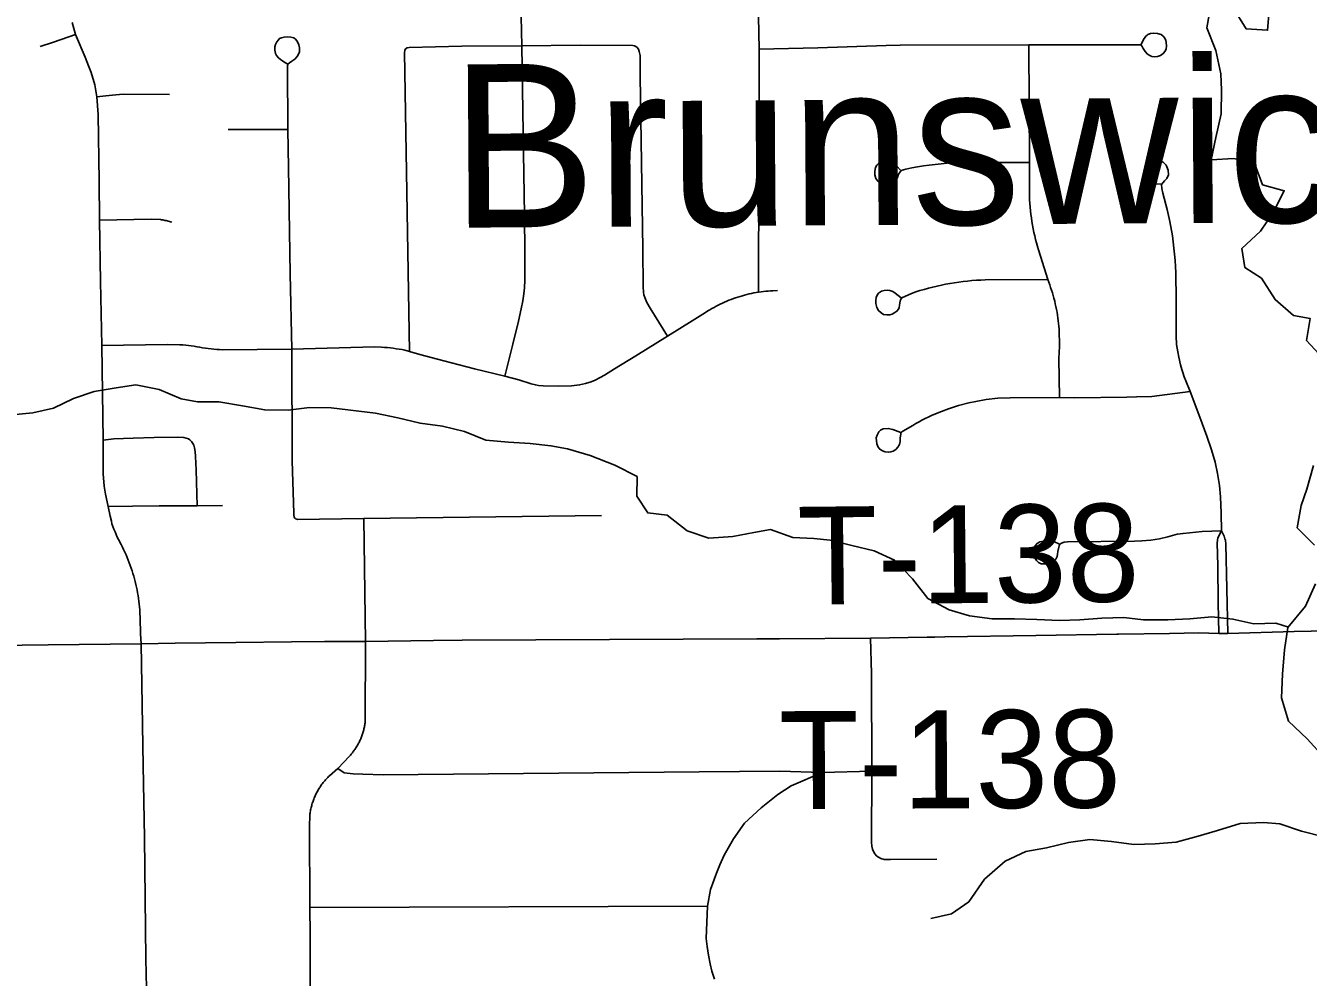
# Model space of a CAD drawing. Extents: x 0 to 34, y 0 to 22.
# Drawn here: x 5.7025 to 6.0747, y 18.6634 to 18.9395 of the extents above; entities that cross this region are included whole.
import ezdxf

# ---------------------------------------------------------------- set-up
doc = ezdxf.new("R2010")
doc.units = 0
for name, color, linetype in [('GM_X_City_Street', 7, 'Continuous'), ('GM_X_Minor_Lake_Text', 7, 'Continuous'), ('GM_X_Minor_River', 7, 'Continuous'), ('GM_X_Township_Road', 7, 'Continuous'), ('GM_X_Township_Road_Text', 7, 'Continuous')]:
    doc.layers.add(name, color=color, linetype=linetype)

msp = doc.modelspace()

# ---------------------------------------------------------------- linework, layer by layer
at = {"layer": 'GM_X_City_Street'}
for p, q in [((5.76126, 18.90929), (5.77862, 18.90938)), ((5.78502, 18.6836), (5.90037, 18.68403))]:
    msp.add_line(p, q, dxfattribs=at)
for points in [[(5.84161, 18.83777), (5.84393, 18.84708), (5.84551, 18.85371), (5.84628, 18.85726), (5.84675, 18.85966), (5.84705, 18.86168), (5.84727, 18.86344), (5.84742, 18.86564), (5.84734, 18.87349), (5.84728, 18.8846), (5.84693, 18.90844), (5.84649, 18.93361), (5.84624, 18.94642), (5.84614, 18.96701), (5.84592, 18.97776), (5.846, 18.98047), (5.8461, 18.98159), (5.84646, 18.98369), (5.84742, 18.98739), (5.84751, 18.98842), (5.84733, 18.99027), (5.84712, 18.99152), (5.84692, 18.99229), (5.84633, 18.9937)], [(5.91519, 18.86214), (5.91534, 18.93265), (5.91473, 18.96601)], [(5.73602, 18.76015), (5.73586, 18.76297), (5.73578, 18.76754), (5.73571, 18.76919), (5.73566, 18.77002), (5.73559, 18.77084), (5.73551, 18.77166), (5.73541, 18.77248), (5.7353, 18.7733), (5.73517, 18.77412), (5.73503, 18.77493), (5.73488, 18.77574), (5.73471, 18.77655), (5.73453, 18.77735), (5.73434, 18.77816), (5.73412, 18.77895), (5.7339, 18.77975), (5.73367, 18.78054), (5.73342, 18.78132), (5.73316, 18.78211), (5.73289, 18.78289), (5.7326, 18.78366), (5.7323, 18.78443), (5.73198, 18.78519), (5.73166, 18.78595), (5.73132, 18.7867), (5.73096, 18.78745), (5.7306, 18.78818), (5.73021, 18.78894), (5.7295, 18.79034), (5.72914, 18.79109), (5.72881, 18.79184), (5.72848, 18.7926), (5.72816, 18.79336), (5.72786, 18.79413), (5.72757, 18.79491), (5.72746, 18.79571), (5.72705, 18.79719), (5.72645, 18.79995), (5.72569, 18.80357), (5.72536, 18.80587), (5.72506, 18.80944), (5.72507, 18.81917), (5.72465, 18.84665), (5.72429, 18.86527), (5.72398, 18.88306), (5.72389, 18.8943), (5.72354, 18.91373), (5.72321, 18.91879), (5.72266, 18.92226), (5.72152, 18.92588), (5.72075, 18.92785), (5.71977, 18.93031), (5.71704, 18.93693), (5.71601, 18.94037)], [(5.7068, 18.93339), (5.71061, 18.93471), (5.71704, 18.93693)], [(5.78061, 18.79658), (5.78048, 18.79685), (5.78042, 18.79711), (5.78039, 18.79729), (5.78031, 18.79807), (5.77986, 18.81325), (5.77974, 18.84565), (5.77932, 18.86749), (5.77876, 18.8983), (5.77862, 18.90938), (5.77847, 18.92759), (5.77865, 18.9283), (5.77905, 18.92864), (5.7798, 18.92919), (5.78062, 18.92975), (5.78136, 18.93051), (5.78175, 18.93119), (5.78196, 18.93187), (5.78203, 18.93238), (5.78199, 18.93306), (5.78183, 18.9339), (5.78154, 18.93456), (5.7812, 18.93503), (5.78088, 18.93553), (5.78034, 18.93589), (5.77948, 18.93612), (5.77866, 18.93619), (5.77751, 18.93617), (5.77677, 18.93592), (5.77615, 18.93569), (5.77586, 18.93531), (5.77539, 18.93481), (5.775, 18.93395), (5.77484, 18.93334), (5.77484, 18.93239), (5.77503, 18.93138), (5.7753, 18.93076), (5.77594, 18.93014), (5.77652, 18.92964), (5.77704, 18.92927), (5.77749, 18.92893), (5.77844, 18.9284)], [(5.91534, 18.93265), (5.93238, 18.93301), (5.95223, 18.93369), (5.95626, 18.93376), (5.99365, 18.93392), (6.02607, 18.93388), (6.02625, 18.9338), (6.02654, 18.93346), (6.02681, 18.93285), (6.02733, 18.93195), (6.02805, 18.93123), (6.02869, 18.93079), (6.02934, 18.93055), (6.03006, 18.93044), (6.03095, 18.93049), (6.03185, 18.93085), (6.03263, 18.93136), (6.03318, 18.93202), (6.03347, 18.93278), (6.03355, 18.93347), (6.03349, 18.93464), (6.03335, 18.93515), (6.03305, 18.93586), (6.03263, 18.93639), (6.03199, 18.93687), (6.03091, 18.9372), (6.02977, 18.93732), (6.02893, 18.93722), (6.02813, 18.93691), (6.0279, 18.93675), (6.02753, 18.93641), (6.02732, 18.93612), (6.02688, 18.93541), (6.0262, 18.93403)], [(5.81387, 18.84495), (5.8125, 18.93171), (5.81259, 18.9323), (5.81276, 18.93273)], [(5.81276, 18.93273), (5.81327, 18.933), (5.81381, 18.93309), (5.82913, 18.93348), (5.84649, 18.93361), (5.86341, 18.93377), (5.87875, 18.9337), (5.8792, 18.9336), (5.87958, 18.93345), (5.88001, 18.93317)], [(5.8888, 18.84933), (5.88372, 18.85747), (5.8828, 18.85917), (5.8822, 18.86057), (5.88195, 18.86139), (5.88182, 18.86215), (5.88171, 18.86365), (5.88161, 18.87471), (5.88085, 18.92476), (5.8808, 18.93076), (5.8806, 18.93196), (5.88032, 18.93263), (5.88001, 18.93317)], [(6.00248, 18.83158), (6.00234, 18.84291), (6.00248, 18.8464), (6.00239, 18.8514), (6.00233, 18.85223), (6.00225, 18.85305), (6.00216, 18.85387), (6.00205, 18.85469), (6.00193, 18.85551), (6.00179, 18.85632), (6.00165, 18.85714), (6.00148, 18.85795), (6.0013, 18.85875), (6.00111, 18.85956), (6.00091, 18.86036), (6.00069, 18.86115), (6.00045, 18.86195), (6.0002, 18.86273), (5.99994, 18.86352), (5.99967, 18.8643), (5.99938, 18.86507), (5.99914, 18.86584), (5.99702, 18.87259), (5.99644, 18.87439), (5.99613, 18.87541), (5.99585, 18.87643), (5.99558, 18.87744), (5.99534, 18.87847), (5.9951, 18.8795), (5.99489, 18.88054), (5.9947, 18.88158), (5.99452, 18.88262), (5.99436, 18.88366), (5.99422, 18.88471), (5.9941, 18.88576), (5.994, 18.88681), (5.99391, 18.88786), (5.99385, 18.88892), (5.9938, 18.88997), (5.99383, 18.89525), (5.99381, 18.8998), (5.99365, 18.93392)], [(5.72321, 18.91879), (5.72579, 18.9191), (5.72868, 18.91941), (5.7308, 18.91957), (5.74424, 18.91952)], [(5.95633, 18.89754), (5.95532, 18.89867), (5.95482, 18.8992), (5.95439, 18.89957), (5.95392, 18.89987), (5.9535, 18.90006), (5.95326, 18.90012), (5.95273, 18.9002), (5.95113, 18.90005), (5.95051, 18.89983), (5.94999, 18.89948), (5.94949, 18.899), (5.94916, 18.89835), (5.94891, 18.89727), (5.94896, 18.89618), (5.94925, 18.8951), (5.94977, 18.89432), (5.95033, 18.8939), (5.95097, 18.89359), (5.95153, 18.89345), (5.95202, 18.89337), (5.95336, 18.89347), (5.95396, 18.89371), (5.95485, 18.89445), (5.95548, 18.89542), (5.95581, 18.89633), (5.95604, 18.89675), (5.95658, 18.89744), (5.95793, 18.89785), (5.95962, 18.89818), (5.96132, 18.89848), (5.96302, 18.89875), (5.96473, 18.89898), (5.96644, 18.89919), (5.96816, 18.89937), (5.96988, 18.89952), (5.9716, 18.89964), (5.97332, 18.89973), (5.97504, 18.89979), (5.99381, 18.8998)], [(6.0495, 18.7929), (6.04941, 18.79799), (6.04926, 18.80277), (6.04893, 18.80602), (6.04833, 18.80953), (6.04763, 18.81286), (6.04657, 18.81637), (6.04523, 18.8204), (6.04319, 18.8259), (6.04038, 18.83328), (6.03912, 18.83644), (6.03872, 18.83755), (6.0383, 18.83887), (6.03801, 18.83968), (6.0376, 18.84104), (6.03709, 18.84331), (6.0368, 18.84484), (6.03648, 18.847), (6.03634, 18.84941), (6.03639, 18.85461), (6.03633, 18.86171), (6.03629, 18.86596), (6.03624, 18.86775), (6.03616, 18.86955), (6.03604, 18.87134), (6.0359, 18.87313), (6.03572, 18.87492), (6.03551, 18.8767), (6.03527, 18.87848), (6.03455, 18.88267), (6.03379, 18.88611), (6.03252, 18.89083), (6.03219, 18.89224), (6.03212, 18.89341), (6.03296, 18.89444), (6.03362, 18.89516), (6.03411, 18.8962), (6.03405, 18.89755), (6.0335, 18.89901), (6.0326, 18.89989), (6.03126, 18.90038), (6.02992, 18.90028), (6.02878, 18.89986), (6.02787, 18.89902), (6.02735, 18.89792), (6.02721, 18.89682), (6.02737, 18.89579), (6.02787, 18.8948), (6.02866, 18.8942), (6.02963, 18.89376), (6.03056, 18.89358), (6.0319, 18.89344)], [(5.72398, 18.88306), (5.73897, 18.88332), (5.74164, 18.88319), (5.74197, 18.88314), (5.7423, 18.88309), (5.74262, 18.88304), (5.74295, 18.88298), (5.74327, 18.88291), (5.74359, 18.88284), (5.74392, 18.88276), (5.745, 18.88249)], [(5.95655, 18.86051), (5.95483, 18.86189), (5.95419, 18.86232), (5.95329, 18.86262), (5.9525, 18.86272), (5.95164, 18.86261), (5.95083, 18.86239), (5.95002, 18.86184), (5.9496, 18.86124), (5.94934, 18.86057), (5.94922, 18.85984), (5.94926, 18.85888), (5.94952, 18.85768), (5.95004, 18.85682), (5.95074, 18.85614), (5.95142, 18.85569), (5.95244, 18.85554), (5.95326, 18.85558), (5.95393, 18.85579), (5.95475, 18.85623), (5.95533, 18.85662), (5.95581, 18.8572), (5.956, 18.85771), (5.95612, 18.85823), (5.9562, 18.85902), (5.95634, 18.85995), (5.95675, 18.86053), (5.95957, 18.86179), (5.96079, 18.8622), (5.96201, 18.86258), (5.96324, 18.86294), (5.96448, 18.86328), (5.96572, 18.8636), (5.96697, 18.8639), (5.96823, 18.86417), (5.96948, 18.86443), (5.97075, 18.86466), (5.97201, 18.86486), (5.97328, 18.86505), (5.97456, 18.86522), (5.97583, 18.86536), (5.97711, 18.86548), (5.97839, 18.86558), (5.97967, 18.86565), (5.98095, 18.86571), (5.99914, 18.86584)], [(5.72465, 18.84665), (5.74364, 18.84695), (5.74732, 18.84688), (5.74814, 18.84682), (5.74897, 18.84675), (5.74979, 18.84667), (5.75061, 18.84657), (5.75143, 18.84645), (5.75225, 18.84632), (5.75306, 18.84618), (5.75388, 18.84604), (5.75469, 18.84591), (5.75551, 18.8458), (5.75633, 18.8457), (5.75716, 18.84561), (5.75798, 18.84554), (5.7588, 18.84548), (5.75963, 18.84544), (5.77974, 18.84565), (5.79685, 18.84613), (5.80387, 18.84625), (5.80582, 18.84618), (5.80668, 18.84612), (5.80752, 18.84605), (5.80837, 18.84597), (5.80922, 18.84587), (5.81006, 18.84575), (5.8109, 18.84562), (5.81175, 18.84548), (5.81258, 18.84532), (5.81387, 18.84495), (5.8169, 18.84407), (5.82388, 18.84218), (5.8328, 18.83994), (5.84161, 18.83777), (5.84563, 18.8367), (5.84923, 18.83558), (5.85043, 18.83521), (5.85135, 18.83507), (5.85273, 18.83499), (5.85727, 18.83484), (5.8609, 18.83497), (5.86327, 18.83525), (5.86499, 18.8356), (5.86662, 18.83612), (5.86779, 18.83658), (5.86925, 18.83734), (5.87051, 18.83808), (5.87339, 18.83988), (5.87961, 18.84369), (5.8888, 18.84933), (5.89597, 18.85381), (5.89979, 18.85626), (5.9005, 18.85671), (5.90108, 18.85706), (5.90168, 18.85741), (5.90227, 18.85774), (5.90288, 18.85807), (5.90348, 18.85838), (5.9041, 18.85869), (5.90472, 18.85898), (5.90535, 18.85926), (5.90598, 18.85953), (5.90661, 18.85979), (5.90725, 18.86004), (5.90789, 18.86028), (5.90854, 18.86051), (5.90919, 18.86072), (5.90984, 18.86093), (5.9105, 18.86112), (5.91116, 18.8613), (5.91183, 18.86147), (5.91249, 18.86162), (5.91317, 18.86177), (5.91384, 18.86191), (5.91451, 18.86203), (5.91519, 18.86214), (5.91594, 18.86225), (5.91662, 18.86233), (5.9173, 18.86241), (5.91798, 18.86247), (5.91866, 18.86252), (5.91935, 18.86256), (5.92072, 18.8626)], [(5.95643, 18.82143), (5.95412, 18.82233), (5.95282, 18.8226), (5.95139, 18.8225), (5.95099, 18.82234), (5.95058, 18.8221), (5.95005, 18.82161), (5.94957, 18.82068), (5.94935, 18.81992), (5.94951, 18.81814), (5.94986, 18.81721), (5.95037, 18.81657), (5.95111, 18.81609), (5.95193, 18.8158), (5.95294, 18.81568), (5.9536, 18.8158), (5.95423, 18.81603), (5.95505, 18.81652), (5.95563, 18.81717), (5.95605, 18.81795), (5.95625, 18.8188), (5.95629, 18.81992), (5.95643, 18.82098), (5.95651, 18.82126), (5.95658, 18.82143), (5.95676, 18.82158), (5.95707, 18.82179), (5.95992, 18.8235), (5.96084, 18.82401), (5.96176, 18.82451), (5.96258, 18.82497), (5.9654, 18.82634), (5.96705, 18.82707), (5.96831, 18.82756), (5.97029, 18.8283), (5.97325, 18.82927), (5.97621, 18.83004), (5.97824, 18.83047), (5.98126, 18.83103), (5.98458, 18.83135), (5.98816, 18.83153), (6.00248, 18.83158), (6.00683, 18.83145), (6.022, 18.83164), (6.02487, 18.83178), (6.02933, 18.83191), (6.04038, 18.83328)], [(5.72507, 18.81917), (5.72815, 18.81957), (5.73371, 18.81982), (5.73979, 18.81994), (5.74664, 18.82006), (5.74842, 18.81998), (5.74915, 18.81982), (5.74975, 18.81957), (5.75016, 18.81928), (5.7507, 18.81882), (5.75109, 18.81828), (5.75132, 18.81775), (5.75153, 18.81697), (5.75171, 18.81593), (5.75186, 18.81445), (5.75201, 18.81055), (5.75235, 18.80013)], [(5.72645, 18.79995), (5.73359, 18.80007), (5.74131, 18.80013), (5.75235, 18.80013), (5.75965, 18.80025)], [(5.78061, 18.79658), (5.78088, 18.79639), (5.78118, 18.79628), (5.78146, 18.79623), (5.80067, 18.79644), (5.86963, 18.79734)], [(5.78523, 18.64429), (5.7851, 18.66871), (5.78506, 18.67583), (5.78502, 18.6836), (5.78489, 18.70723), (5.78498, 18.71034), (5.78502, 18.71066), (5.78506, 18.71099), (5.78511, 18.71131), (5.78517, 18.71163), (5.78523, 18.71196), (5.7853, 18.71228), (5.78537, 18.7126), (5.78545, 18.71291), (5.78553, 18.71323), (5.78562, 18.71354), (5.78571, 18.71386), (5.78582, 18.71417), (5.78592, 18.71448), (5.78603, 18.71479), (5.78615, 18.71509), (5.78627, 18.71539), (5.7864, 18.7157), (5.78653, 18.716), (5.78667, 18.71629), (5.78681, 18.71659), (5.78696, 18.71688), (5.78711, 18.71717), (5.78727, 18.71746), (5.78743, 18.71774), (5.7876, 18.71802), (5.78777, 18.7183), (5.78795, 18.71857), (5.78813, 18.71885), (5.78832, 18.71911), (5.78851, 18.71938), (5.78871, 18.71964), (5.78891, 18.7199), (5.78911, 18.72015), (5.78932, 18.72041), (5.78953, 18.72065), (5.78976, 18.7209), (5.78998, 18.72114), (5.7902, 18.72138), (5.79044, 18.72161), (5.79067, 18.72183), (5.79311, 18.72394), (5.79649, 18.72757), (5.79675, 18.72785), (5.79695, 18.72807), (5.79714, 18.7283), (5.79733, 18.72853), (5.79752, 18.72876), (5.7977, 18.729), (5.79788, 18.72924), (5.79805, 18.72948), (5.79822, 18.72972), (5.79838, 18.72997), (5.79854, 18.73022), (5.7987, 18.73048), (5.79885, 18.73074), (5.799, 18.73099), (5.79914, 18.73125), (5.79928, 18.73152), (5.79941, 18.73179), (5.79954, 18.73205), (5.79966, 18.73233), (5.79978, 18.7326), (5.7999, 18.73287), (5.8, 18.73315), (5.80011, 18.73343), (5.80021, 18.73371), (5.80031, 18.73399), (5.8004, 18.73428), (5.80048, 18.73456), (5.80056, 18.73485), (5.80064, 18.73514), (5.8007, 18.73543), (5.80077, 18.73572), (5.80083, 18.73601), (5.80088, 18.7363), (5.80093, 18.7366), (5.80098, 18.73689), (5.80101, 18.73719), (5.80105, 18.73748), (5.80113, 18.76084), (5.80067, 18.79644)], [(6.00251, 18.78907), (6.00084, 18.78978), (6.00017, 18.78995), (5.9991, 18.79001), (5.99789, 18.78993), (5.99678, 18.78968), (5.99601, 18.78923), (5.99531, 18.78846), (5.99492, 18.78741), (5.99496, 18.78614), (5.99529, 18.78519), (5.99581, 18.7843), (5.99645, 18.78368), (5.99723, 18.78337), (5.998, 18.78329), (5.99936, 18.78335), (6.00055, 18.78381), (6.00116, 18.78436), (6.00145, 18.78471), (6.00179, 18.7855), (6.0019, 18.78615), (6.00206, 18.78691), (6.00233, 18.78818), (6.00244, 18.78858), (6.00257, 18.78895), (6.0029, 18.78925), (6.00311, 18.78936), (6.00383, 18.78957), (6.00485, 18.78973), (6.02426, 18.78993), (6.02644, 18.78999), (6.02904, 18.7902), (6.03152, 18.79057), (6.0339, 18.79119), (6.03668, 18.79189), (6.03835, 18.79217), (6.04392, 18.79275), (6.0495, 18.7929)], [(6.04876, 18.76315), (6.04858, 18.7721), (6.04842, 18.78287), (6.04822, 18.78932), (6.04832, 18.79021), (6.04849, 18.79087), (6.0495, 18.7929)], [(6.05131, 18.7631), (6.05078, 18.78906), (6.05063, 18.79018), (6.05053, 18.79059), (6.05026, 18.79135), (6.0495, 18.7929)], [(5.96693, 18.69765), (5.95352, 18.69751), (5.95161, 18.69757), (5.95068, 18.69787), (5.94955, 18.69847), (5.9488, 18.6993), (5.94825, 18.7005), (5.94804, 18.70145), (5.94795, 18.70259), (5.94805, 18.72319), (5.94795, 18.75148), (5.94768, 18.76173)], [(5.73767, 18.65601), (5.73739, 18.66874), (5.73707, 18.70395), (5.73667, 18.72473), (5.73602, 18.76015)], [(5.79311, 18.72394), (5.79491, 18.72271), (5.79758, 18.72236), (5.80042, 18.72227), (5.80625, 18.72209), (5.89799, 18.72297), (5.92132, 18.72313), (5.93361, 18.72276), (5.94805, 18.72319)], [(5.90241, 18.66279), (5.90161, 18.66516), (5.90114, 18.66723), (5.90063, 18.66976), (5.90024, 18.67229), (5.89998, 18.67461), (5.90037, 18.68403), (5.90123, 18.6888), (5.90295, 18.69357), (5.90398, 18.69596), (5.90521, 18.69878), (5.9079, 18.70355), (5.91108, 18.70808), (5.91592, 18.71255), (5.92075, 18.7164), (5.92461, 18.71891), (5.93361, 18.72276)]]:
    msp.add_lwpolyline(points, dxfattribs=at)
at = {"layer": 'GM_X_Minor_River'}
for points in [[(6.04645, 18.94534), (6.04527, 18.93887), (6.04788, 18.93228), (6.04936, 18.92549), (6.04947, 18.92075), (6.04944, 18.91392), (6.0479, 18.90705), (6.04653, 18.90057), (6.05295, 18.9009), (6.05903, 18.89972), (6.06145, 18.89332), (6.06773, 18.89157), (6.06447, 18.88523), (6.06081, 18.87983), (6.05544, 18.87478), (6.05633, 18.86929), (6.06113, 18.86618), (6.06505, 18.86001), (6.07045, 18.85539), (6.0752, 18.85455), (6.07421, 18.84808), (6.07906, 18.84287)], [(6.06348, 18.94498), (6.06288, 18.93814), (6.05663, 18.93856), (6.0527, 18.94492)], [(6.06899, 18.76494), (6.06531, 18.76609), (6.05889, 18.76594), (6.05281, 18.76732), (6.04674, 18.76793), (6.04032, 18.76741), (6.0339, 18.76707), (6.0269, 18.7671), (6.02121, 18.76772), (6.01479, 18.76757), (6.00837, 18.76705), (6.00251, 18.76691), (5.99589, 18.76714), (5.98945, 18.76737), (5.98302, 18.76741), (5.97638, 18.7682), (5.97048, 18.76996), (5.96435, 18.77324), (5.95987, 18.77902), (5.95464, 18.7844), (5.94872, 18.78711), (5.94225, 18.78866), (5.93597, 18.79023), (5.93124, 18.79069), (5.92518, 18.79093), (5.9187, 18.79324), (5.9138, 18.79237), (5.90777, 18.79128), (5.90079, 18.79074), (5.8945, 18.79287), (5.88872, 18.79748), (5.88303, 18.79811), (5.87989, 18.80297), (5.87995, 18.80866), (5.87345, 18.81193), (5.86638, 18.8148), (5.85972, 18.81673), (5.85497, 18.81757), (5.84891, 18.81819), (5.84266, 18.81861), (5.83602, 18.81922), (5.82991, 18.82173), (5.82345, 18.82329), (5.817, 18.82409), (5.81053, 18.82565), (5.80407, 18.82702), (5.79118, 18.82862), (5.78494, 18.82866), (5.77871, 18.82795), (5.7719, 18.82798), (5.76544, 18.82916), (5.75861, 18.83033), (5.75237, 18.83037), (5.74762, 18.83121), (5.74132, 18.83391), (5.73448, 18.83527), (5.72883, 18.83438), (5.72242, 18.83329), (5.71642, 18.83125), (5.71062, 18.82846), (5.7046, 18.82718), (5.69762, 18.82645)], [(6.07618, 18.81188), (6.07426, 18.805), (6.07266, 18.80022), (6.07149, 18.79374), (6.07652, 18.78874)], [(6.07678, 18.77755), (6.0739, 18.77103), (6.06875, 18.76484), (6.06776, 18.75836), (6.06717, 18.75133), (6.06695, 18.74449), (6.06899, 18.73771), (6.07441, 18.73252), (6.07926, 18.72713)], [(6.09284, 18.70392), (6.09204, 18.7058), (6.08526, 18.70469), (6.07922, 18.70417), (6.07275, 18.70573), (6.06646, 18.70786), (6.06173, 18.70832), (6.05492, 18.70797), (6.04835, 18.70592), (6.04272, 18.70427), (6.03633, 18.70261), (6.03029, 18.70209), (6.02405, 18.70194), (6.0176, 18.70274), (6.01135, 18.70336), (6.00512, 18.70246), (5.99873, 18.70098), (5.9927, 18.69989), (5.98672, 18.6971), (5.98078, 18.69184), (5.97621, 18.68528), (5.97118, 18.68175), (5.96516, 18.68047)]]:
    msp.add_lwpolyline(points, dxfattribs=at)
at = {"layer": 'GM_X_Township_Road'}
msp.add_line((5.96635, 18.76208), (5.96923, 18.76212), dxfattribs=at)
for points in [[(6.01965, 18.76289), (6.03438, 18.76315), (6.0429, 18.76328), (6.04876, 18.76315), (6.05131, 18.7631), (6.07061, 18.76369), (6.08043, 18.76384), (6.08299, 18.76387), (6.08877, 18.76402), (6.10083, 18.76412), (6.11352, 18.76422), (6.12216, 18.76428), (6.13641, 18.7644), (6.14354, 18.76448), (6.15687, 18.76455), (6.16641, 18.76463), (6.17753, 18.76472), (6.1871, 18.76477), (6.20586, 18.76486), (6.22121, 18.76493), (6.22973, 18.76498), (6.29265, 18.76521)], [(5.78921, 18.76075), (5.7982, 18.7608), (5.80113, 18.76084), (5.82083, 18.76105), (5.82924, 18.76114), (5.91471, 18.76157), (5.92131, 18.7616)], [(5.92131, 18.7616), (5.94768, 18.76173), (5.96412, 18.76204), (5.96635, 18.76208)], [(5.96923, 18.76212), (5.99562, 18.7625), (6.0191, 18.76288), (6.01965, 18.76289)], [(5.68631, 18.75957), (5.70905, 18.75985), (5.73602, 18.76015), (5.74589, 18.76027)], [(5.74589, 18.76027), (5.76356, 18.76046), (5.77971, 18.76065), (5.78921, 18.76075)]]:
    msp.add_lwpolyline(points, dxfattribs=at)

# ---------------------------------------------------------------- texts
at = {"layer": 'GM_X_Minor_Lake_Text'}
msp.add_text('Brunswick', height=0.047373, rotation=0.3645, dxfattribs=at).set_placement((5.82594, 18.88083))
at = {"layer": 'GM_X_Township_Road_Text'}
for rotation, p in [(0.5709, (5.92659, 18.77144)), (0.2814, (5.92115, 18.71215))]:
    msp.add_text('T-138', height=0.028409, rotation=rotation, dxfattribs=at).set_placement(p)

doc.saveas('drawing.dxf')
